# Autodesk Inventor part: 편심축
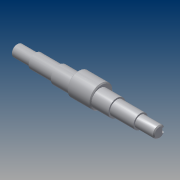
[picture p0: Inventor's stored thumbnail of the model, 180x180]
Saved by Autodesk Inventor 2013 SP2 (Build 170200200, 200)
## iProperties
Created: 2014-12
Part Number: 편심축
Material: 알루미늄 6061
Document SubType Name: Modeling
Designer: CADB302
Density: 2.71 g/cm^3
Mass: 90.367 g
Surface Area: 86.7923 cm^2
Volume: 33.3457 cm^3
Author: CADB302
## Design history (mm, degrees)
sketch "스케치1"
  geometry: L1 (-75.5, 0)-(75.5, 0); L2 (-75.5, 0)-(-75.5, 6); L3 (-75.5, 6)-(-55.5, 6); L4 (-55.5, 6)-(-55.5, 7.5); L5 (-55.5, 7.5)-(-30.5, 7.5); L6 (-30.5, 7.5)-(-30.5, 9); L7 (30.5, 9)-(30.5, 7.5); L8 (30.5, 7.5)-(55.5, 7.5); L9 (55.5, 7.5)-(55.5, 6); L10 (55.5, 6)-(75.5, 6); L11 (75.5, 6)-(75.5, 0); L12 (-30.5, 9)-(30.5, 9); L13 (12.5, 2)-(-12.5, 2); L14 (-12.5, 2)-(-12.5, 14); L15 (-12.5, 14)-(12.5, 14); L16 (12.5, 14)-(12.5, 2); L17 (-75.5, 6)-(-61.5, 6); L18 (-61.5, 6)-(-61.5, 3); L19 (-61.5, 3)-(-75.5, 3); L20 (-75.5, 3)-(-75.5, 6); L21 (75.5, 6)-(61.5, 6); L22 (61.5, 6)-(61.5, 3); L23 (61.5, 3)-(75.5, 3); L24 (75.5, 3)-(75.5, 6); 2 further points
  constraints: 48 end point, 13 parallel, 6 perpendicular, 4 horizontal, 1 coincident, 1 collinear, 1 midpoint
  dimensions: "d0" = 151 distance of L1.start L1.end; "d7" = 12 diameter of L10 L1; "d8" = 12 diameter of L3 L1; "d9" = 15 diameter of L5 L1; "d10" = 15 diameter of L8 L1; "d13" = 18 diameter of L12 L1; "d14" = 20 distance of L2.end L3.end; "d15" = 25 distance of L4.end L5.end; "d16" = 20 distance of L9.end L10.end; "d17" = 25 distance of L7.end L8.end; "d18" = 4 diameter of L13 L1; "d19" = 12 distance of L13.end L14.end; "d20" = 18 distance between parallel lines of L14 L6; "d21" = 18 distance between parallel lines of L7 L16; "d22" = 14 distance of L2.end L17.end; "d23" = 3 distance of L17.end L18.end; "d24" = 14 distance of L10.end L21.end; "d25" = 3 distance of L21.end L22.end
revolve "회전1" stored, may be unused: angle "d26" = 90 deg
revolve "회전2" stored, may be unused: angle "d27" = 90 deg
extrude "돌출1" cut sketch "스케치1" stored distance "d28" = 5; taper "d29" = 0 deg
extrude "돌출2" cut sketch "스케치1" stored distance "d30" = 5; taper "d31" = 0 deg
fillet "모깎기1" dims "d32" = 2.5
chamfer "모따기1" distance "d33" = 1; stored, may be unused: second distance "d34" = 2, angle "d35" = 45 deg
node "솔리드1"
